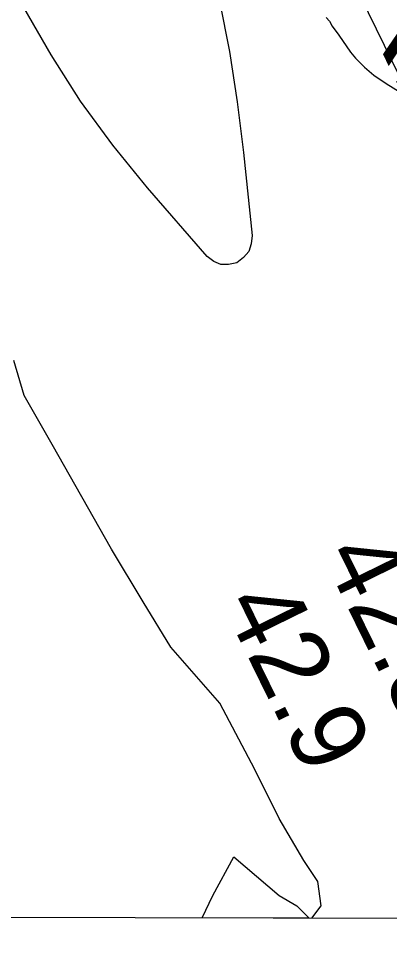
# Model space of a CAD drawing. Extents: x 3177185 to 3215018, y 812988 to 838321.
# Drawn here: x 3197446 to 3197779, y 818326 to 819169 of the extents above; entities that cross this region are included whole.
import ezdxf

# ---------------------------------------------------------------- set-up
doc = ezdxf.new("R2010")
doc.units = 0
for name, color, linetype in [('V-GRID-FRAM', 7, 'Continuous'), ('V-RIVR-RANG', 7, 'Continuous'), ('V-SITE-VEGE', 7, 'Continuous'), ('V-TOPO-MINR', 7, 'Continuous'), ('V-TOPO-WATR-IDEN', 7, 'Continuous')]:
    doc.layers.add(name, color=color, linetype=linetype)

msp = doc.modelspace()

# ---------------------------------------------------------------- linework, layer by layer
at = {"layer": 'V-GRID-FRAM'}
msp.add_lwpolyline([(3181402.42, 836586.07), (3212801.61, 836513), (3212767.22, 818326.14), (3181352.16, 818399.25), (3181402.42, 836586.07)], dxfattribs=at)
at = {"layer": 'V-SITE-VEGE'}
for p, q in [((3197721.87, 819170.42), (3197724.73, 819167.21)), ((3197724.73, 819167.21), (3197727.19, 819162.79)), ((3197727.19, 819162.79), (3197733.34, 819154.76)), ((3197733.34, 819154.76), (3197743.59, 819139.5)), ((3197743.59, 819139.5), (3197748.09, 819133.88)), ((3197748.09, 819133.88), (3197756.25, 819125.87)), ((3197756.25, 819125.87), (3197764.8, 819118.68)), ((3197764.8, 819118.68), (3197775.79, 819111.1)), ((3197775.79, 819111.1), (3197794.5, 819099.55)), ((3197450.49, 818830.94), (3197441.07, 818862.36)), ((3197475.6, 818786.96), (3197450.49, 818830.94)), ((3197528.98, 818692.73), (3197475.6, 818786.96)), ((3197557.23, 818645.61), (3197528.98, 818692.73)), ((3197582.35, 818604.77), (3197557.23, 818645.61)), ((3197626.3, 818554.51), (3197582.35, 818604.77)), ((3197657.7, 818494.82), (3197626.3, 818554.51)), ((3197679.67, 818450.84), (3197657.7, 818494.82)), ((3197701.65, 818413.14), (3197679.67, 818450.84)), ((3197620.02, 818381.73), (3197638.86, 818416.29)), ((3197638.86, 818416.29), (3197679.67, 818381.73)), ((3197714.21, 818394.3), (3197701.65, 818413.14)), ((3197717.35, 818372.31), (3197714.21, 818394.3)), ((3197610.4, 818361.42), (3197620.02, 818381.73)), ((3197679.67, 818381.73), (3197695.37, 818372.31)), ((3197695.37, 818372.31), (3197706.48, 818361.19)), ((3197709.01, 818361.19), (3197717.35, 818372.31)), ((3197706.48, 818361.19), (3197610.4, 818361.42)), ((3198087.87, 818360.31), (3197709.01, 818361.19))]:
    msp.add_line(p, q, dxfattribs=at)
at = {"layer": 'V-TOPO-MINR'}
for points in [[(3197539.23, 819625.55), (3197844.87, 819000.56), (3197870.23, 818949.23), (3197895.87, 818898.04), (3197921.93, 818847.06), (3197948.26, 818796.22), (3197966.2, 818761.92), (3197983.92, 818728.42), (3198001.83, 818695.02), (3198020.05, 818661.79), (3198038.46, 818628.67), (3198052.11, 818604.36), (3198077.6, 818559.22), (3198103.24, 818514.16), (3198129.1, 818469.23), (3198155.09, 818424.38), (3198192.58, 818360.06)], [(3197625.9, 819185.09), (3197634.88, 819140.08), (3197641.88, 819094.72), (3197647.56, 819049.14), (3197655.2, 818974.67), (3197654.48, 818967.03), (3197652.21, 818960.27), (3197647.61, 818954.81), (3197641.47, 818950.22), (3197634.13, 818948.46), (3197627.17, 818948.5), (3197620.77, 818951.24), (3197614.75, 818955.79), (3197561.15, 819017.52), (3197530.14, 819055.83), (3197500.97, 819095.4), (3197474.58, 819136.87), (3197450.04, 819179.62)]]:
    msp.add_lwpolyline(points, dxfattribs=at)

# ---------------------------------------------------------------- texts
at = {"layer": 'V-RIVR-RANG'}
for s, p in [('42.8', (3197717.94, 818687.44)), ('42.9', (3197628.13, 818643.45))]:
    msp.add_text(s, height=67, rotation=296.10833, dxfattribs=at).set_placement(p)
at = {"layer": 'V-TOPO-WATR-IDEN'}
msp.add_text('L.W.R.P.', height=83, rotation=295.7117, dxfattribs=at).set_placement((3197646.52, 819399.96))

doc.saveas('drawing.dxf')
